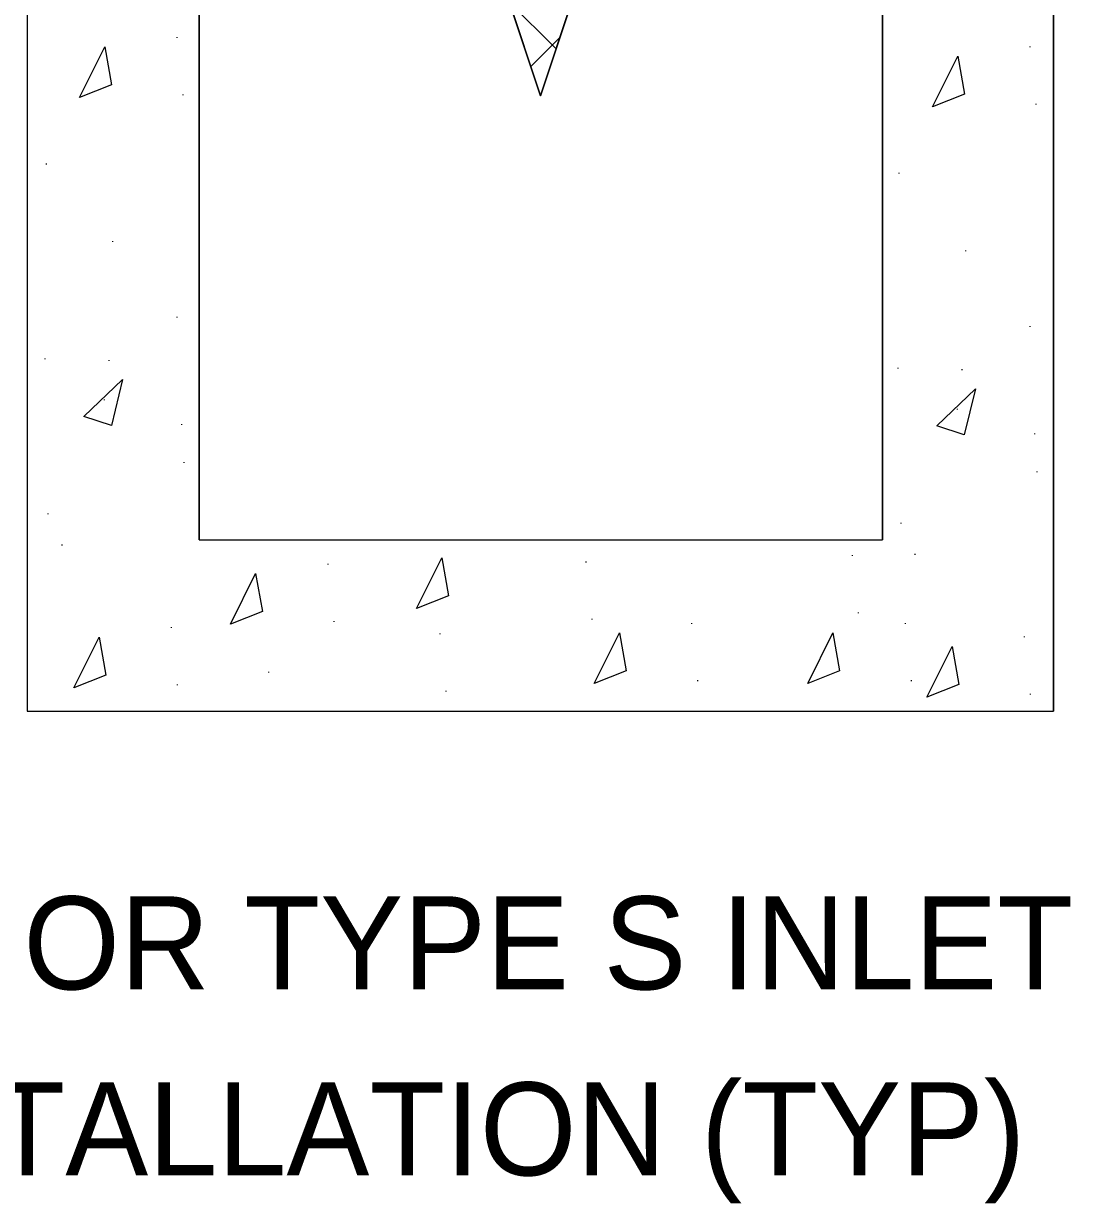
# Model space of a CAD drawing. Extents: x 636183 to 639890, y 299162 to 300538.
# Drawn here: x 636862 to 636911.2, y 299588.4 to 299643.9 of the extents above; entities that cross this region are included whole.
import ezdxf

# ---------------------------------------------------------------- set-up
doc = ezdxf.new("R2010")
doc.units = 0
doc.layers.add('1', color=7, linetype='Continuous')
doc.layers.add('Default', color=7, linetype='Continuous')

msp = doc.modelspace()

# ---------------------------------------------------------------- linework, layer by layer
at = {"layer": '1'}
for p, q in [((636870.253, 299688.701), (636886.308, 299640.467)), ((636886.308, 299640.467), (636902.397, 299688.701)), ((636887.042, 299642.67), (636884.842, 299644.87)), ((636885.851, 299641.838), (636887.222, 299643.21))]:
    msp.add_line(p, q, dxfattribs=at)
msp.add_lwpolyline([(636870.253, 299688.701), (636902.397, 299688.701), (636886.308, 299640.467)], close=True, dxfattribs=at)
at = {"layer": 'Default'}
for p, q in [((636862.173, 299691.953), (636862.173, 299611.541)), ((636910.442, 299611.541), (636910.442, 299691.953)), ((636910.442, 299691.953), (636910.442, 299611.541)), ((636910.442, 299611.541), (636910.442, 299691.953)), ((636870.253, 299688.945), (636870.253, 299619.586)), ((636870.253, 299619.586), (636870.253, 299688.596)), ((636870.253, 299688.596), (636870.253, 299619.586)), ((636902.397, 299619.586), (636902.397, 299688.945)), ((636902.397, 299688.596), (636902.397, 299619.586)), ((636902.397, 299619.586), (636902.397, 299688.596)), ((636869.225, 299643.187), (636869.225, 299643.222)), ((636864.629, 299640.378), (636865.818, 299642.757)), ((636865.818, 299642.757), (636866.133, 299640.973)), ((636909.343, 299642.749), (636909.343, 299642.784)), ((636904.747, 299639.94), (636905.936, 299642.319)), ((636905.936, 299642.319), (636906.251, 299640.535)), ((636866.133, 299640.973), (636864.629, 299640.378)), ((636869.505, 299640.493), (636869.505, 299640.528)), ((636886.308, 299640.467), (636886.308, 299640.467)), ((636906.251, 299640.535), (636904.747, 299639.94)), ((636909.623, 299640.055), (636909.623, 299640.09)), ((636863.069, 299637.24), (636863.069, 299637.275)), ((636903.187, 299636.803), (636903.187, 299636.838)), ((636866.203, 299633.592), (636866.203, 299633.627)), ((636906.321, 299633.155), (636906.321, 299633.19)), ((636869.225, 299630.035), (636869.225, 299630.07)), ((636909.343, 299629.597), (636909.343, 299629.632)), ((636862.999, 299628.111), (636862.999, 299628.076)), ((636866.007, 299628.041), (636866.007, 299628.006)), ((636903.117, 299627.674), (636903.117, 299627.639)), ((636906.125, 299627.604), (636906.125, 299627.569)), ((636864.832, 299625.379), (636866.651, 299627.128)), ((636866.651, 299627.128), (636866.126, 299624.959)), ((636904.95, 299624.941), (636906.769, 299626.69)), ((636906.769, 299626.69), (636906.244, 299624.521)), ((636865.811, 299626.148), (636865.811, 299626.183)), ((636866.126, 299624.959), (636864.832, 299625.379)), ((636905.929, 299625.711), (636905.929, 299625.746)), ((636869.449, 299624.994), (636869.449, 299625.029)), ((636906.244, 299624.521), (636904.95, 299624.941)), ((636909.567, 299624.556), (636909.567, 299624.591)), ((636869.554, 299623.21), (636869.554, 299623.245)), ((636909.672, 299622.772), (636909.672, 299622.808)), ((636863.153, 299620.797), (636863.153, 299620.832)), ((636903.271, 299620.359), (636903.271, 299620.394)), ((636863.818, 299619.328), (636863.818, 299619.363)), ((636870.253, 299619.586), (636902.397, 299619.586)), ((636880.474, 299616.367), (636881.663, 299618.745)), ((636881.663, 299618.745), (636881.978, 299616.961)), ((636888.455, 299618.53), (636888.455, 299618.565)), ((636900.987, 299618.829), (636900.987, 299618.864)), ((636903.936, 299618.89), (636903.936, 299618.925)), ((636871.723, 299615.622), (636872.913, 299618.001)), ((636872.913, 299618.001), (636873.228, 299616.217)), ((636876.32, 299618.431), (636876.32, 299618.466)), ((636881.978, 299616.961), (636880.474, 299616.367)), ((636873.228, 299616.217), (636871.723, 299615.622)), ((636888.734, 299615.837), (636888.734, 299615.872)), ((636901.267, 299616.135), (636901.267, 299616.171)), ((636868.959, 299615.445), (636868.959, 299615.48)), ((636876.6, 299615.737), (636876.6, 299615.772)), ((636893.428, 299615.644), (636893.428, 299615.679)), ((636903.474, 299615.644), (636903.474, 299615.679)), ((636864.363, 299612.637), (636865.552, 299615.015)), ((636865.552, 299615.015), (636865.867, 299613.231)), ((636881.591, 299615.147), (636881.591, 299615.182)), ((636888.832, 299612.836), (636890.021, 299615.214)), ((636890.021, 299615.214), (636890.336, 299613.43)), ((636898.878, 299612.836), (636900.067, 299615.214)), ((636900.067, 299615.214), (636900.382, 299613.43)), ((636909.077, 299615.008), (636909.077, 299615.043)), ((636904.481, 299612.199), (636905.67, 299614.578)), ((636905.67, 299614.578), (636905.985, 299612.794)), ((636865.867, 299613.231), (636864.363, 299612.637)), ((636873.535, 299613.356), (636873.535, 299613.391)), ((636890.336, 299613.43), (636888.832, 299612.836)), ((636900.382, 299613.43), (636898.878, 299612.836)), ((636869.239, 299612.752), (636869.239, 299612.787)), ((636881.871, 299612.454), (636881.871, 299612.489)), ((636893.708, 299612.951), (636893.708, 299612.986)), ((636903.754, 299612.951), (636903.754, 299612.986)), ((636905.985, 299612.794), (636904.481, 299612.199)), ((636909.357, 299612.314), (636909.357, 299612.349)), ((636862.173, 299611.541), (636910.442, 299611.541))]:
    msp.add_line(p, q, dxfattribs=at)

# ---------------------------------------------------------------- texts
for s, p in [('TYPE M OR TYPE S INLET ', (636838.599, 299598.456)), ('INSTALLATION (TYP)', (636850.643, 299589.712))]:
    msp.add_text(s, height=4.37214, dxfattribs=at).set_placement(p)

doc.saveas('drawing.dxf')
